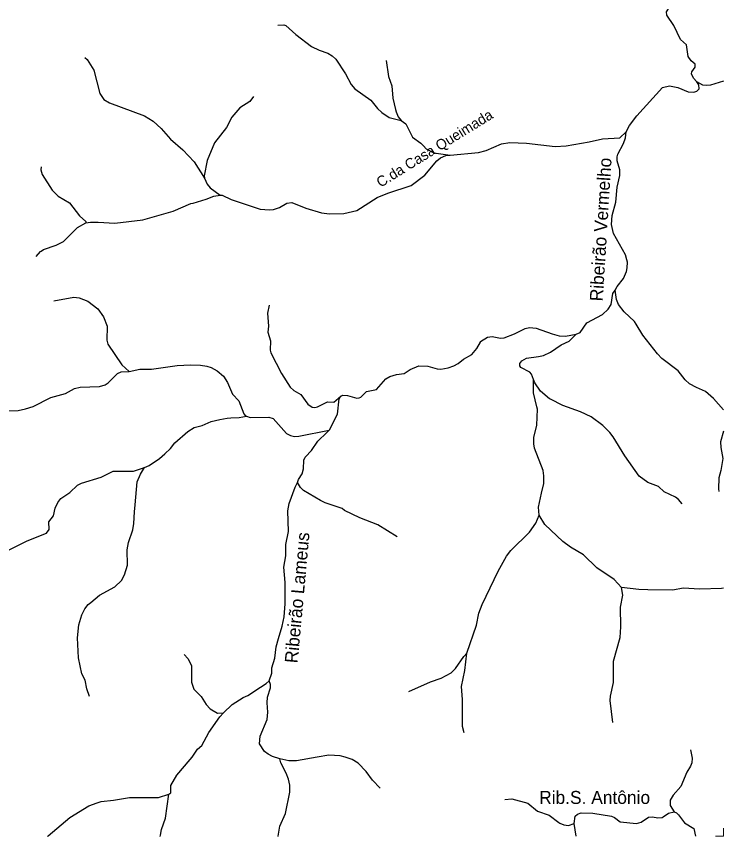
# Model space of a CAD drawing. Extents: x 473.9 to 500, y 7733.1 to 7760.8.
# Drawn here: x 494.55 to 500, y 7733.15 to 7739.47 of the extents above; entities that cross this region are included whole.
import ezdxf
from ezdxf.enums import TextEntityAlignment as Align

# ---------------------------------------------------------------- set-up
doc = ezdxf.new("R2010")
doc.units = 0
doc.header["$LTSCALE"] = 0.032
doc.layers.add('61', color=7, linetype='Continuous')
doc.layers.add('63', color=7, linetype='Continuous', lineweight=13)
doc.layers.add('7', color=7, linetype='Continuous', lineweight=25)

msp = doc.modelspace()

# ---------------------------------------------------------------- linework, layer by layer
at = {"layer": '63'}
msp.add_lwpolyline([(499.9368, 7733.1574), (499.9984, 7733.1574), (499.9984, 7733.2181)], dxfattribs=at)
at = {"layer": '7'}
msp.add_line((498.8642, 7733.1575), (498.8498, 7733.2562), dxfattribs=at)
for points in [[(499.7943, 7738.9681), (499.7676, 7738.9941), (499.7518, 7739.0295), (499.7547, 7739.0446), (499.7805, 7739.0805), (499.7807, 7739.1029), (499.7507, 7739.128), (499.726, 7739.1629), (499.7138, 7739.2511), (499.6679, 7739.2941), (499.6171, 7739.4013), (499.5636, 7739.4799), (499.5607, 7739.5068), (499.5833, 7739.541), (499.661, 7739.6005), (499.6789, 7739.6206), (499.6817, 7739.6378), (499.6721, 7739.6759), (499.6826, 7739.7071), (499.7265, 7739.7405)], [(496.5676, 7739.4031), (496.6119, 7739.4068), (496.6293, 7739.4005), (496.705, 7739.3321), (496.8272, 7739.239), (496.8846, 7739.2112), (496.9519, 7739.1879), (496.9843, 7739.1674), (497.014, 7739.1405), (497.0881, 7739.0299), (497.1315, 7738.9471), (497.159, 7738.9142), (497.2838, 7738.8253), (497.3351, 7738.7613), (497.3677, 7738.7315), (497.425, 7738.6932), (497.5172, 7738.6694)], [(495.0808, 7739.1539), (495.0979, 7739.1401), (495.1494, 7739.057), (495.1957, 7738.8778), (495.2253, 7738.8314), (495.2698, 7738.8055), (495.5386, 7738.7055), (495.606, 7738.6639), (495.667, 7738.6078), (495.7388, 7738.5262), (495.835, 7738.4446), (495.9227, 7738.3521), (496.002, 7738.2249)], [(497.4021, 7739.1306), (497.4192, 7739.007), (497.4448, 7738.9368), (497.4536, 7738.8422), (497.4729, 7738.755), (497.4771, 7738.736), (497.4947, 7738.6978), (497.5172, 7738.6694)], [(499.25, 7738.5831), (499.2745, 7738.6297), (499.3327, 7738.7059), (499.5298, 7738.9225), (499.5844, 7738.9363), (499.6475, 7738.9225), (499.7282, 7738.8904), (499.7715, 7738.8875), (499.7938, 7738.8942), (499.8124, 7738.9135), (499.8103, 7738.9427), (499.7943, 7738.9681)], [(500, 7738.9725), (499.9984, 7738.972), (499.8981, 7738.9413), (499.8649, 7738.9388), (499.8409, 7738.9421), (499.7943, 7738.9681)], [(496.3799, 7738.855), (496.3514, 7738.8163), (496.2742, 7738.7672), (496.2129, 7738.6939), (496.1725, 7738.6151), (496.0787, 7738.498), (496.0217, 7738.3605), (495.9982, 7738.2422), (496.002, 7738.2249)], [(497.5172, 7738.6694), (497.5516, 7738.644), (497.6049, 7738.5397), (497.6671, 7738.4935), (497.6874, 7738.4733), (497.71, 7738.4508), (497.7675, 7738.42), (497.8937, 7738.4028)], [(497.8937, 7738.4028), (498.113, 7738.4216), (498.1711, 7738.4386), (498.289, 7738.4905), (498.3528, 7738.5001), (498.4821, 7738.4937), (498.7033, 7738.4698), (498.7887, 7738.4749), (498.9645, 7738.5042), (499.0679, 7738.5276), (499.2012, 7738.5361), (499.25, 7738.5831)], [(499.1643, 7737.3638), (499.1793, 7737.3913), (499.2281, 7737.4518), (499.2523, 7737.5071), (499.2584, 7737.5353), (499.259, 7737.578), (499.2547, 7737.5962), (499.2453, 7737.6358), (499.1514, 7737.7992), (499.1374, 7737.8688), (499.1422, 7737.9385), (499.1709, 7738.0404), (499.1791, 7738.1565), (499.1998, 7738.2452), (499.2013, 7738.2884), (499.1807, 7738.3595), (499.1799, 7738.3891), (499.1845, 7738.4097), (499.2294, 7738.491), (499.2447, 7738.5347), (499.25, 7738.5831)], [(496.1216, 7738.0942), (496.139, 7738.094), (496.2065, 7738.062), (496.4318, 7737.9871), (496.5029, 7737.9805), (496.5344, 7737.9844), (496.5783, 7738), (496.637, 7738.0334), (496.6743, 7738.0368), (496.782, 7737.9939), (496.9021, 7737.957), (496.9637, 7737.9502), (497.0755, 7737.9534), (497.1757, 7737.977), (497.3322, 7738.075), (497.4131, 7738.1087), (497.5929, 7738.1677), (497.6992, 7738.2494), (497.7917, 7738.3595), (497.8184, 7738.3822), (497.8608, 7738.3992), (497.8937, 7738.4028)], [(494.7427, 7738.3131), (494.7402, 7738.2883), (494.7504, 7738.2529), (494.8283, 7738.1324), (494.8737, 7738.0873), (494.9632, 7738.0343), (495.0397, 7737.9354), (495.0879, 7737.8904), (495.0884, 7737.8801)], [(496.002, 7738.2249), (496.0217, 7738.18), (496.0455, 7738.1499), (496.1216, 7738.0942)], [(495.0884, 7737.8801), (495.1227, 7737.8875), (495.1825, 7737.8875), (495.3103, 7737.878), (495.528, 7737.9045), (495.7599, 7737.97), (495.8978, 7738.0293), (495.914, 7738.0339), (496.0142, 7738.0626), (496.0749, 7738.0869), (496.1216, 7738.0942)], [(494.7046, 7737.6219), (494.7393, 7737.6596), (494.7451, 7737.6637), (494.763, 7737.6764), (494.86, 7737.7085), (494.9154, 7737.737), (494.9534, 7737.775), (495.0238, 7737.8454), (495.0884, 7737.8801)], [(498.8647, 7737.0247), (498.8961, 7737.0378), (498.9468, 7737.1116), (499.0678, 7737.1765), (499.1111, 7737.2174), (499.1349, 7737.2535), (499.1474, 7737.3376), (499.1643, 7737.3638)], [(500, 7736.4419), (499.9227, 7736.5281), (499.8611, 7736.581), (499.7902, 7736.6118), (499.7375, 7736.6421), (499.7037, 7736.6715), (499.6513, 7736.7417), (499.5254, 7736.8374), (499.4902, 7736.8725), (499.3774, 7737.0163), (499.3267, 7737.0998), (499.313, 7737.1224), (499.2347, 7737.1953), (499.1917, 7737.2523), (499.1761, 7737.2902), (499.1643, 7737.3638)], [(494.8411, 7737.2815), (494.9953, 7737.3078), (495.0354, 7737.3038), (495.1021, 7737.277), (495.1797, 7737.218), (495.2249, 7737.1569), (495.253, 7737.0849), (495.2487, 7736.9765), (495.2586, 7736.9471), (495.3656, 7736.787), (495.4214, 7736.7375)], [(496.5007, 7737.2476), (496.4859, 7737.1857), (496.4938, 7737.0843), (496.4899, 7737.0398), (496.5106, 7736.9727), (496.5075, 7736.9018), (496.514, 7736.8795), (496.5961, 7736.72), (496.6613, 7736.6154), (496.6889, 7736.5898), (496.7439, 7736.559), (496.7981, 7736.4848), (496.8308, 7736.4626), (496.8511, 7736.4597), (496.8724, 7736.465), (496.9487, 7736.5037), (496.9977, 7736.4997), (497.0519, 7736.5454)], [(497.0519, 7736.5454), (497.0678, 7736.554), (497.1037, 7736.5519), (497.1742, 7736.5318), (497.1939, 7736.5324), (497.2065, 7736.538), (497.2487, 7736.5822), (497.3256, 7736.5978), (497.398, 7736.679), (497.4288, 7736.699), (497.4809, 7736.7137), (497.5406, 7736.7201), (497.5856, 7736.751), (497.6521, 7736.7794), (497.7226, 7736.778), (497.7932, 7736.7571), (497.8232, 7736.7546), (497.8777, 7736.7636), (497.9216, 7736.7797), (497.9548, 7736.7967), (497.9971, 7736.8324), (498.0603, 7736.8659), (498.0995, 7736.9131), (498.127, 7736.9632), (498.1287, 7736.9663), (498.1819, 7737.0017), (498.2172, 7737.0048), (498.2819, 7736.9929), (498.3096, 7736.9957), (498.3897, 7737.0263), (498.4711, 7737.0665), (498.5049, 7737.0745), (498.5576, 7737.0703), (498.6789, 7737.0253), (498.7336, 7737.0112), (498.7821, 7737.0073), (498.8647, 7737.0247)], [(498.5354, 7736.6753), (498.5207, 7736.7161), (498.5087, 7736.7313), (498.4385, 7736.7672), (498.4308, 7736.781), (498.4301, 7736.7984), (498.4454, 7736.8196), (498.4808, 7736.8385), (498.5747, 7736.8509), (498.6123, 7736.8603), (498.6677, 7736.8847), (498.7489, 7736.9428), (498.811, 7736.971), (498.8647, 7737.0247)], [(495.4214, 7736.7375), (495.504, 7736.7531), (495.5941, 7736.7539), (495.7919, 7736.7827), (495.8942, 7736.7875), (495.9706, 7736.7859), (496.0206, 7736.7786), (496.0542, 7736.7678), (496.0983, 7736.7426), (496.1479, 7736.6996), (496.18, 7736.6511), (496.2182, 7736.5625), (496.2676, 7736.5112), (496.3048, 7736.4112), (496.3145, 7736.3973), (496.3252, 7736.393)], [(494.3693, 7736.4469), (494.4776, 7736.4345), (494.5663, 7736.4364), (494.624, 7736.4477), (494.6818, 7736.4679), (494.8194, 7736.5348), (494.9304, 7736.5667), (495.0001, 7736.6063), (495.0443, 7736.6159), (495.1929, 7736.6208), (495.2361, 7736.6345), (495.2605, 7736.6501), (495.333, 7736.7221), (495.3612, 7736.7327), (495.4214, 7736.7375)], [(499.6821, 7735.7167), (499.6523, 7735.7506), (499.6283, 7735.7675), (499.5419, 7735.8091), (499.4989, 7735.8494), (499.4156, 7735.8804), (499.3499, 7735.9303), (499.2387, 7736.0874), (499.1499, 7736.2338), (499.125, 7736.2666), (499.0693, 7736.3199), (498.979, 7736.3884), (498.897, 7736.4258), (498.7623, 7736.4747), (498.6669, 7736.5221), (498.66, 7736.5255), (498.5894, 7736.5857), (498.5462, 7736.6492), (498.5354, 7736.6753)], [(498.5786, 7735.629), (498.5753, 7735.6925), (498.5982, 7735.7986), (498.6145, 7735.8744), (498.6161, 7735.9327), (498.6094, 7735.9732), (498.5437, 7736.146), (498.5376, 7736.1786), (498.5392, 7736.2275), (498.5617, 7736.324), (498.5672, 7736.4467), (498.5627, 7736.4647), (498.536, 7736.5728), (498.5354, 7736.6753)], [(496.964, 7736.2862), (496.9648, 7736.2878), (497.0269, 7736.4084), (497.0399, 7736.5245), (497.0519, 7736.5454)], [(495.54, 7735.997), (495.5765, 7736.0134), (495.6545, 7736.0658), (495.6965, 7736.1026), (495.7404, 7736.1433), (495.7743, 7736.1876), (495.8735, 7736.2745), (495.9233, 7736.3039), (495.9841, 7736.3215), (496.0531, 7736.3509), (496.1198, 7736.3675), (496.1771, 7736.3778), (496.2051, 7736.3788), (496.2688, 7736.3812), (496.3252, 7736.393)], [(496.3252, 7736.393), (496.3524, 7736.3811), (496.4986, 7736.3849), (496.531, 7736.3748), (496.6343, 7736.2581), (496.6643, 7736.2425), (496.6963, 7736.2352), (496.7287, 7736.2375), (496.9617, 7736.2857), (496.964, 7736.2862)], [(496.7194, 7735.8807), (496.7257, 7735.9048), (496.7542, 7735.9469), (496.7648, 7735.9874), (496.7682, 7736.053), (496.7775, 7736.0776), (496.78, 7736.0801), (496.8263, 7736.1266), (496.876, 7736.1996), (496.9444, 7736.2669), (496.964, 7736.2862)], [(500, 7736.2764), (499.9768, 7736.1937), (499.9784, 7736.1498), (499.9936, 7736.0662), (499.9799, 7735.9738), (499.9632, 7735.9176), (499.96, 7735.8331), (499.964, 7735.811)], [(494.3667, 7735.2345), (494.3953, 7735.2545), (494.4371, 7735.316), (494.4923, 7735.3607), (494.6351, 7735.432), (494.7838, 7735.4917), (494.8044, 7735.5195), (494.8036, 7735.5797), (494.8396, 7735.6239), (494.8511, 7735.6825), (494.8717, 7735.7284), (494.8952, 7735.7581), (494.9656, 7735.8038), (495.0234, 7735.8606), (495.0541, 7735.8763), (495.2048, 7735.9228), (495.2996, 7735.9689), (495.4546, 7735.9674), (495.54, 7735.997)], [(495.1165, 7734.2345), (495.0964, 7734.2919), (495.0819, 7734.3589), (495.0574, 7734.4086), (495.0306, 7734.5315), (495.0226, 7734.684), (495.0339, 7734.7845), (495.056, 7734.8618), (495.0796, 7734.9076), (495.1067, 7734.9419), (495.1252, 7734.9574), (495.1931, 7735.0143), (495.3115, 7735.0768), (495.3618, 7735.1277), (495.3851, 7735.171), (495.409, 7735.2457), (495.4067, 7735.3616), (495.4158, 7735.42), (495.45, 7735.5173), (495.4587, 7735.5645), (495.462, 7735.6553), (495.4673, 7735.7105), (495.4841, 7735.8861), (495.5078, 7735.9451), (495.54, 7735.997)], [(496.4999, 7734.355), (496.5212, 7734.4125), (496.5203, 7734.4549), (496.5428, 7734.5278), (496.5527, 7734.6168), (496.5719, 7734.6791), (496.6012, 7734.7742), (496.6149, 7734.8461), (496.6221, 7734.9467), (496.6222, 7735.1123), (496.6117, 7735.2288), (496.6285, 7735.3159), (496.6294, 7735.4032), (496.6477, 7735.5035), (496.6438, 7735.663), (496.6542, 7735.7207), (496.6997, 7735.8451), (496.7194, 7735.8807)], [(497.4856, 7735.4632), (497.3368, 7735.5542), (497.1971, 7735.6093), (497.0802, 7735.6651), (497.0614, 7735.6802), (496.9307, 7735.7245), (496.8945, 7735.7425), (496.764, 7735.8202), (496.7419, 7735.8433), (496.7194, 7735.8807)], [(498.0223, 7734.5663), (498.0956, 7734.7835), (498.1154, 7734.8747), (498.1397, 7734.9407), (498.2638, 7735.1986), (498.3283, 7735.314), (498.3601, 7735.3577), (498.5062, 7735.4979), (498.5527, 7735.5679), (498.5786, 7735.629)], [(499.2126, 7735.0732), (499.1579, 7735.1343), (499.0228, 7735.2251), (498.9219, 7735.3256), (498.8198, 7735.3828), (498.7628, 7735.4271), (498.6244, 7735.559), (498.5786, 7735.629)], [(499.1481, 7734.0337), (499.1253, 7734.2038), (499.1277, 7734.237), (499.1517, 7734.341), (499.1517, 7734.5045), (499.2023, 7734.6867), (499.2095, 7734.7696), (499.2063, 7734.9224), (499.224, 7735.0142), (499.2126, 7735.0732)], [(500, 7735.0667), (499.9835, 7735.066), (499.8164, 7735.0588), (499.6884, 7735.0678), (499.6078, 7735.0533), (499.4173, 7735.0556), (499.3482, 7735.0565), (499.2126, 7735.0732)], [(495.8463, 7734.5557), (495.873, 7734.5272), (495.9029, 7734.4708), (495.9013, 7734.3433), (495.9207, 7734.289), (495.9751, 7734.2328), (496.0159, 7734.1719), (496.0467, 7734.1374), (496.103, 7734.1049), (496.1491, 7734.1082)], [(497.5752, 7734.272), (497.7436, 7734.3468), (497.8243, 7734.3739), (497.9012, 7734.4144), (497.9342, 7734.4482), (497.9989, 7734.5416), (498.0223, 7734.5663)], [(498.0018, 7733.9538), (497.9895, 7734.0015), (497.9891, 7734.2098), (497.9803, 7734.3092), (498.0067, 7734.4344), (498.0223, 7734.5663)], [(496.1491, 7734.1082), (496.2143, 7734.1707), (496.3006, 7734.2266), (496.3355, 7734.2409), (496.4336, 7734.3053), (496.4771, 7734.3338), (496.4999, 7734.355)], [(496.5822, 7733.7523), (496.5255, 7733.7703), (496.4928, 7733.789), (496.4644, 7733.8103), (496.4257, 7733.8687), (496.4315, 7733.9267), (496.4842, 7734.0558), (496.489, 7734.1123), (496.4835, 7734.1836), (496.4866, 7734.2287), (496.509, 7734.3013), (496.509, 7734.326), (496.4999, 7734.355)], [(495.7264, 7733.4801), (495.7423, 7733.4916), (495.7426, 7733.548), (495.7892, 7733.628), (495.8914, 7733.7477), (495.9074, 7733.7664), (495.9479, 7733.828), (495.9818, 7733.856), (496.036, 7733.9548), (496.1199, 7734.0757), (496.1491, 7734.1082)], [(499.7453, 7733.8217), (499.7579, 7733.7593), (499.7546, 7733.7219), (499.7449, 7733.698), (499.7178, 7733.6503), (499.6699, 7733.5407), (499.6118, 7733.4747), (499.5878, 7733.4348), (499.5892, 7733.3928), (499.6204, 7733.3439)], [(496.5691, 7733.1558), (496.5694, 7733.1572), (496.5831, 7733.2339), (496.625, 7733.3329), (496.6582, 7733.4963), (496.6581, 7733.5507), (496.6484, 7733.596), (496.6311, 7733.6434), (496.5894, 7733.7236), (496.5822, 7733.7523)], [(497.3553, 7733.5272), (497.2962, 7733.5895), (497.2477, 7733.6563), (497.1843, 7733.7197), (497.1389, 7733.7481), (497.0858, 7733.7669), (497.0462, 7733.7776), (496.959, 7733.7808), (496.8707, 7733.7658), (496.7102, 7733.7384), (496.6511, 7733.7368), (496.5822, 7733.7523)], [(494.7924, 7733.1544), (494.7989, 7733.16), (494.9635, 7733.3018), (495.1114, 7733.3906), (495.1743, 7733.415), (495.2059, 7733.4241), (495.3021, 7733.4337), (495.4247, 7733.4561), (495.6469, 7733.4562), (495.7264, 7733.4801)], [(495.66, 7733.1551), (495.6622, 7733.1653), (495.6713, 7733.2078), (495.7016, 7733.2957), (495.7264, 7733.4801)], [(498.3155, 7733.4413), (498.3683, 7733.4456), (498.4913, 7733.4127), (498.5674, 7733.3515), (498.6572, 7733.3202), (498.7322, 7733.2618), (498.7383, 7733.2571), (498.7684, 7733.2448), (498.805, 7733.2397), (498.8498, 7733.2562)], [(498.8498, 7733.2562), (498.8578, 7733.3117), (498.875, 7733.3274), (498.9031, 7733.3382), (498.9921, 7733.335), (499.1357, 7733.3126), (499.1602, 7733.3018), (499.2045, 7733.2692), (499.3282, 7733.254), (499.3663, 7733.2645), (499.4208, 7733.3028), (499.4533, 7733.3071), (499.4942, 7733.2983), (499.5269, 7733.3006), (499.5354, 7733.3064), (499.5762, 7733.3343), (499.6204, 7733.3439)], [(499.6204, 7733.3439), (499.6362, 7733.3386), (499.6532, 7733.3232), (499.6983, 7733.2606), (499.7697, 7733.2174), (499.7836, 7733.1587), (499.7837, 7733.1582)]]:
    msp.add_lwpolyline(points, dxfattribs=at)

# ---------------------------------------------------------------- texts
at = {"layer": '61'}
for s, height, rotation, p in [('C.da Casa Queimada', 0.08, 31.737, (497.7948, 7738.4211)), ('Ribeirão Vermelho', 0.1, 86.424, (499.1032, 7737.827)), ('Ribeirão Lameus', 0.1, 84.753, (496.765, 7734.99))]:
    msp.add_text(s, height=height, rotation=rotation, dxfattribs=at).set_placement(p, align=Align.CENTER)
msp.add_text('Rib.S. Antônio', height=0.1, dxfattribs=at).set_placement((499.0067, 7733.406), align=Align.CENTER)

doc.saveas('drawing.dxf')
